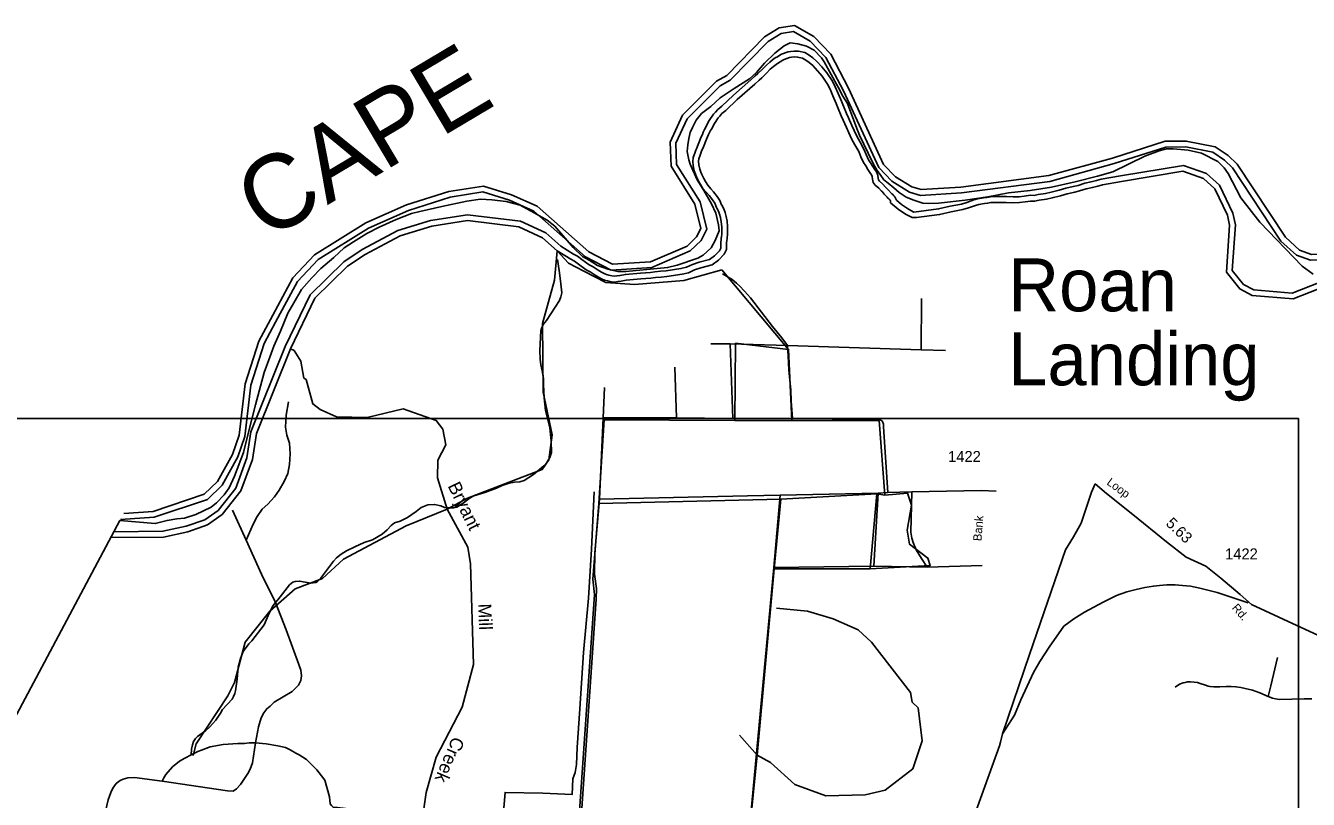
# Model space of a CAD drawing. Extents: x 2225501 to 2309677, y 165449 to 227696.
# Drawn here: x 2251795 to 2266364, y 218912 to 227696 of the extents above; entities that cross this region are included whole.
import ezdxf

# ---------------------------------------------------------------- set-up
doc = ezdxf.new("R2010")
doc.units = 0
for name, color, linetype in [('E_RDY_CMT_EOP', 7, 'Continuous'), ('MARK ENDS WORD SYMBOL CELL', 7, 'Continuous'), ('Old_Level_18', 7, 'Continuous'), ('Old_Level_3', 7, 'Continuous'), ('Old_Level_33', 7, 'Continuous'), ('Old_Level_51', 7, 'Continuous'), ('Old_Level_63', 7, 'Continuous'), ('P_HYD_Drop_Inlet_Grate_2_Wide_Slot_and_Sag_Grates_840_22_48_Dia_Apron_CELL', 7, 'Continuous'), ('P_HYD_Pipe_Pipe_Removal', 7, 'Continuous'), ('P_RDY_Concrete_Monolithic_Island', 7, 'Continuous'), ('P_RDY_Dimension_Text', 7, 'Continuous'), ('Prop Support', 7, 'Continuous'), ('Scratch_Level_1', 7, 'Continuous'), ('Typical Terminator CELL', 7, 'Continuous')]:
    doc.layers.add(name, color=color, linetype=linetype)

msp = doc.modelspace()

# ---------------------------------------------------------------- linework, layer by layer
at = {"layer": 'Old_Level_18'}
msp.add_line((2266181, 224660), (2266624, 224833), dxfattribs=at)
for points in [[(2264160, 226130), (2263429, 225928), (2262423, 225796), (2261960, 225768), (2261832, 225805), (2261633, 225930), (2261485, 226084), (2261083, 226956), (2260885, 227334), (2260705, 227521), (2260515, 227628), (2260376, 227607), (2260229, 227516), (2259798, 227078), (2259682, 227011), (2259308, 226639), (2259180, 226362), (2259189, 226120), (2259456, 225697), (2259533, 225387), (2259468, 225257), (2259343, 225138), (2258907, 224950), (2258444, 224921), (2258154, 225073), (2257568, 225591), (2257289, 225716), (2256989, 225808), (2256618, 225750), (2256144, 225598), (2255687, 225397), (2255119, 225042), (2254882, 224793), (2254659, 224378)], [(2261686, 225714), (2261667, 225754), (2261655, 225765), (2261644, 225779), (2261634, 225786), (2261629, 225792), (2261595, 225827), (2261570, 225856), (2261563, 225864), (2261531, 225898), (2261492, 225930), (2261482, 225944), (2261478, 225966), (2261473, 225998), (2261459, 226035), (2261437, 226066), (2261418, 226096), (2261392, 226137), (2261369, 226174), (2261341, 226233), (2261316, 226295), (2261272, 226373), (2261234, 226441), (2261205, 226505), (2261179, 226564), (2261142, 226651), (2261118, 226700), (2261086, 226780), (2261061, 226839), (2261023, 226926), (2260991, 227000), (2260958, 227065), (2260895, 227160), (2260839, 227227), (2260780, 227289), (2260735, 227331), (2260693, 227359), (2260644, 227390), (2260572, 227405), (2260525, 227407), (2260487, 227404), (2260454, 227398), (2260381, 227372), (2260360, 227359), (2260334, 227343), (2260309, 227330), (2260277, 227307), (2260247, 227282), (2260208, 227248), (2260163, 227202), (2260111, 227153), (2260081, 227127), (2260033, 227081), (2259833, 226906), (2259702, 226783), (2259658, 226745), (2259629, 226713), (2259608, 226690), (2259560, 226619), (2259526, 226554), (2259515, 226537)], [(2259515, 226537), (2259506, 226517), (2259492, 226487), (2259481, 226462), (2259468, 226434), (2259432, 226345), (2259413, 226296), (2259407, 226284), (2259394, 226249), (2259375, 226198), (2259372, 226155), (2259377, 226107), (2259387, 226049), (2259402, 226009), (2259416, 225978), (2259439, 225931), (2259461, 225894), (2259488, 225847), (2259527, 225800), (2259559, 225766), (2259597, 225719), (2259621, 225682), (2259640, 225633), (2259646, 225624), (2259664, 225589), (2259677, 225555), (2259686, 225516), (2259696, 225468), (2259701, 225413), (2259702, 225374), (2259702, 225331), (2259697, 225295), (2259696, 225288), (2259693, 225263), (2259691, 225238), (2259689, 225217)], [(2264160, 226130), (2264747, 226318), (2264972, 226320), (2265278, 226258), (2265413, 226170), (2265504, 226083), (2266053, 225251), (2266229, 225090), (2266387, 225032), (2266613, 225036)], [(2261884, 225580), (2262164, 225616), (2262294, 225646), (2262423, 225670), (2262485, 225690), (2262566, 225717), (2262608, 225728), (2262674, 225741), (2262711, 225745), (2262752, 225753), (2262835, 225755), (2262934, 225756), (2263010, 225752), (2263080, 225753), (2263138, 225760), (2263207, 225770), (2263248, 225768), (2263296, 225779), (2263379, 225792), (2263442, 225804), (2263532, 225828), (2263609, 225850), (2263694, 225869), (2263748, 225883), (2263824, 225906), (2263896, 225923), (2263956, 225937), (2264010, 225954), (2264230, 225992)], [(2266181, 224660), (2265746, 224697), (2265627, 224759), (2265500, 224918), (2265536, 225436), (2265506, 225568), (2265353, 225884), (2265208, 226019), (2264945, 226109), (2264230, 225992)], [(2261686, 225714), (2261744, 225667), (2261821, 225613), (2261884, 225580)], [(2254742, 224052), (2255025, 224640), (2255410, 225015), (2255617, 225154), (2256023, 225371), (2256392, 225485), (2256813, 225548), (2257416, 225476), (2257702, 225344), (2257872, 225193)], [(2257872, 225193), (2258019, 225101), (2258064, 225077), (2258112, 225040), (2258197, 224980), (2258240, 224957), (2258299, 224921), (2258336, 224899), (2258374, 224877), (2258391, 224869), (2258417, 224863), (2258454, 224854), (2258485, 224851), (2258510, 224854), (2258546, 224861), (2258607, 224872), (2258779, 224887), (2258891, 224894), (2258942, 224900), (2259006, 224907), (2259071, 224914), (2259238, 224938), (2259301, 224954), (2259369, 224983), (2259446, 225009), (2259563, 225040)], [(2259563, 225040), (2259619, 225083), (2259676, 225140), (2259690, 225168), (2259689, 225217)], [(2254659, 224378), (2254633, 224330), (2254503, 224089), (2254353, 223615), (2254283, 223032), (2254205, 222801), (2254025, 222480), (2253859, 222318), (2253256, 222115), (2252872, 222088)], [(2252798, 221950), (2253354, 221955), (2253618, 222013), (2253829, 222086), (2253980, 222193), (2254182, 222446), (2254307, 222788), (2254354, 223083), (2254742, 224052)]]:
    msp.add_lwpolyline(points, dxfattribs=at)
at = {"layer": 'Old_Level_3'}
for p, q in [((2261970, 224598), (2261968, 224016)), ((2259797, 224082), (2259579, 224082)), ((2260447, 224063), (2259797, 224082)), ((2259797, 224082), (2259828, 223235)), ((2261968, 224016), (2260447, 224063)), ((2262242, 224008), (2261968, 224016)), ((2259188, 223242), (2259169, 223819)), ((2258354, 223243), (2258369, 223587)), ((2258354, 223243), (2258311, 222319)), ((2259188, 223242), (2258354, 223243)), ((2259828, 223235), (2259188, 223242)), ((2259995, 223235), (2259828, 223235)), ((2260505, 223234), (2259995, 223235)), ((2259995, 222357), (2258311, 222319)), ((2260366, 222366), (2259995, 222357)), ((2260366, 222366), (2260291, 221543)), ((2260366, 222366), (2261478, 222388)), ((2261429, 221560), (2261478, 222388)), ((2261478, 222388), (2261588, 222397)), ((2261588, 222397), (2261859, 222404)), ((2254298, 221856), (2254144, 222194)), ((2260291, 221543), (2259848, 216791)), ((2260291, 221543), (2261429, 221560)), ((2261429, 221560), (2262034, 221549)), ((2262034, 221549), (2262658, 221566))]:
    msp.add_line(p, q, dxfattribs=at)
for points in [[(2257853, 224916), (2257836, 225040)], [(2254631, 221147), (2254660, 221179), (2254793, 221348), (2254829, 221379), (2254857, 221387), (2254906, 221391), (2255035, 221366), (2255090, 221375), (2255110, 221385), (2255144, 221419), (2255188, 221481), (2255291, 221616), (2255326, 221655), (2255380, 221697), (2255440, 221734), (2255533, 221778), (2255641, 221827), (2255734, 221860), (2255844, 221921), (2255899, 221971), (2255947, 222022), (2255985, 222052), (2256050, 222072), (2256132, 222111), (2256231, 222180), (2256287, 222226), (2256363, 222257), (2256439, 222260), (2256509, 222244), (2256551, 222226), (2256595, 222221), (2256655, 222221), (2256693, 222230), (2256763, 222276), (2256844, 222337), (2256886, 222359), (2257010, 222396), (2257141, 222445), (2257207, 222474), (2257288, 222500), (2257346, 222513), (2257406, 222515), (2257458, 222532), (2257562, 222601), (2257679, 222697), (2257716, 222736), (2257748, 222792), (2257768, 222848), (2257764, 222980), (2257749, 223130), (2257700, 223327), (2257685, 223471), (2257675, 223623), (2257675, 223689), (2257662, 223777), (2257647, 223845), (2257639, 223909), (2257634, 224009), (2257646, 224231), (2257652, 224257), (2257672, 224303), (2257709, 224349), (2257859, 224574), (2257875, 224618), (2257885, 224664), (2257870, 224800), (2257853, 224916)], [(2259708, 224877), (2259819, 224814), (2259869, 224774), (2259907, 224739), (2259960, 224683), (2260026, 224606), (2260279, 224280), (2260384, 224153), (2260447, 224063)], [(2260447, 224063), (2260453, 224003), (2260454, 223947), (2260463, 223790), (2260485, 223556), (2260490, 223434), (2260505, 223234)], [(2254779, 223426), (2254752, 223274), (2254746, 223139), (2254763, 223046), (2254790, 222954), (2254801, 222835), (2254790, 222715), (2254773, 222612), (2254730, 222520), (2254676, 222422), (2254622, 222346), (2254546, 222265), (2254481, 222205), (2254426, 222124), (2254377, 222037), (2254298, 221856)], [(2261588, 222397), (2261540, 223143), (2261539, 223173), (2261527, 223203), (2261501, 223224), (2261455, 223232), (2261407, 223230), (2260505, 223234)], [(2258253, 222403), (2258221, 221754), (2258188, 221195), (2258132, 220579), (2258091, 219939), (2258059, 219501), (2258051, 219307), (2258035, 219217), (2258010, 219144), (2258002, 218966), (2257670, 218982), (2257241, 218990), (2257079, 217094), (2256973, 215935), (2256868, 214921), (2256860, 214840)], [(2261859, 222404), (2261849, 221944), (2261860, 221878), (2261876, 221828), (2261911, 221744), (2261970, 221645), (2262034, 221549)], [(2261859, 222404), (2262649, 222420), (2262820, 222412)], [(2258311, 222319), (2258261, 221709), (2258257, 221469), (2258278, 221307), (2258273, 221183), (2258098, 218590), (2257998, 217156), (2257958, 216666)], [(2254631, 221147), (2254474, 221468), (2254298, 221856)], [(2262890, 219654), (2263026, 219868), (2263098, 220043), (2263244, 220354), (2263315, 220476), (2263421, 220641), (2263587, 220880), (2263700, 220961), (2263820, 221036), (2264033, 221150), (2264184, 221225), (2264304, 221267), (2264409, 221294), (2264507, 221316), (2264605, 221333), (2264675, 221339), (2264757, 221347), (2264850, 221348), (2264935, 221341), (2265025, 221331), (2265131, 221311), (2265328, 221259), (2265680, 221142)], [(2253673, 219416), (2253679, 219482), (2253688, 219530), (2253700, 219568), (2253725, 219604), (2253747, 219625), (2253841, 219693), (2253886, 219734), (2253956, 219812), (2253976, 219846), (2254007, 219892), (2254029, 219933), (2254140, 220048), (2254157, 220080), (2254171, 220114), (2254179, 220144), (2254196, 220276), (2254207, 220412), (2254234, 220510), (2254265, 220592), (2254329, 220677), (2254362, 220711), (2254505, 220892), (2254560, 221025), (2254607, 221111), (2254631, 221147)], [(2254406, 219552), (2254438, 219736), (2254471, 219838), (2254499, 219894), (2254534, 219941), (2254572, 219969), (2254618, 220014), (2254821, 220137), (2254864, 220177), (2254892, 220208), (2254920, 220262), (2254929, 220314), (2254921, 220378), (2254898, 220444), (2254753, 220838), (2254631, 221147)], [(2265907, 220081), (2265939, 220199), (2266012, 220521)], [(2265907, 220081), (2265812, 220123), (2265728, 220151), (2265647, 220170), (2265596, 220181), (2265542, 220190), (2265486, 220195), (2265430, 220195), (2265357, 220191), (2265289, 220191), (2265248, 220192), (2265225, 220196), (2265194, 220207), (2265136, 220226), (2265104, 220238), (2265067, 220243), (2265024, 220246), (2264993, 220245), (2264965, 220239), (2264941, 220234), (2264901, 220218), (2264850, 220186)], [(2266403, 220052), (2266316, 220054), (2266035, 220047), (2265992, 220053), (2265958, 220059), (2265907, 220081)], [(2253346, 219117), (2254088, 219007), (2254150, 219006), (2254188, 219030), (2254234, 219081), (2254319, 219205), (2254346, 219254), (2254373, 219326), (2254406, 219552)], [(2253346, 219117), (2253363, 219156), (2253387, 219194), (2253462, 219280), (2253544, 219347), (2253603, 219381), (2253673, 219416)], [(2253673, 219416), (2253749, 219457), (2253791, 219469), (2253892, 219510), (2254040, 219533), (2254206, 219546), (2254280, 219547), (2254332, 219553), (2254406, 219552)], [(2254406, 219552), (2254528, 219541), (2254658, 219518), (2254746, 219499), (2254800, 219473), (2254865, 219436), (2254901, 219418), (2254983, 219363), (2255102, 219248), (2255156, 219178), (2255191, 219129), (2255244, 218939), (2255253, 218861), (2255267, 218841), (2255287, 218823), (2255307, 218818), (2255337, 218818), (2255753, 218769)], [(2252643, 218484), (2252670, 218612), (2252685, 218712), (2252732, 218907), (2252763, 218989), (2252786, 219039), (2252822, 219091), (2252870, 219126), (2252904, 219142), (2252956, 219156), (2253031, 219161), (2253346, 219117)]]:
    msp.add_lwpolyline(points, dxfattribs=at)
at = {"layer": 'Old_Level_33'}
for points in [[(2263944, 222495), (2263902, 222401), (2263782, 222047), (2263698, 221893), (2263607, 221746), (2263196, 220557), (2262890, 219654)], [(2266578, 220728), (2266027, 220979), (2265717, 221126), (2265589, 221237), (2265371, 221424), (2265200, 221558), (2264977, 221663), (2264754, 221837), (2264371, 222147), (2264070, 222386), (2263944, 222495)], [(2262890, 219654), (2262869, 219562), (2262857, 219519), (2262522, 218596), (2262202, 217703), (2262033, 217188), (2261762, 216419), (2260197, 211949), (2260121, 211814), (2260069, 211762), (2259986, 211722), (2259866, 211664), (2259693, 211606), (2259466, 211514), (2259333, 211475), (2259261, 211462), (2259169, 211468), (2258985, 211468), (2258808, 211471), (2258716, 211462), (2258607, 211410)]]:
    msp.add_lwpolyline(points, dxfattribs=at)
at = {"layer": 'Old_Level_51'}
for points in [[(2252865, 222076), (2253266, 222042), (2253401, 222079), (2253513, 222098), (2253599, 222104), (2253727, 222147), (2253900, 222231), (2253964, 222279), (2254051, 222368), (2254106, 222450), (2254167, 222583), (2254269, 222849), (2254319, 223052), (2254404, 223390), (2254503, 223757), (2254570, 223934), (2254613, 224058), (2254689, 224228), (2254772, 224431), (2254839, 224550), (2254928, 224702), (2255046, 224833), (2255148, 224938), (2255294, 225065), (2255411, 225172), (2255517, 225243), (2255670, 225338), (2255811, 225409), (2256005, 225497), (2256176, 225564), (2256272, 225587), (2256521, 225641), (2256807, 225703), (2256960, 225726), (2257088, 225719), (2257253, 225701), (2257413, 225658), (2257569, 225571), (2257720, 225489), (2257806, 225419), (2258014, 225177), (2258121, 225076), (2258195, 225033), (2258290, 224974), (2258408, 224931), (2258520, 224905), (2258612, 224904), (2258850, 224926), (2259086, 224950), (2259196, 224975), (2259431, 225055), (2259490, 225091), (2259582, 225172), (2259625, 225258), (2259670, 225365), (2259666, 225434), (2259635, 225566), (2259586, 225674), (2259497, 225825), (2259422, 225946), (2259342, 226122), (2259326, 226174), (2259309, 226267), (2259315, 226341), (2259328, 226413), (2259341, 226482), (2259369, 226540), (2259412, 226624), (2259473, 226699), (2259579, 226777), (2259684, 226878), (2259841, 226981), (2260018, 227091), (2260095, 227165), (2260188, 227271), (2260306, 227382), (2260410, 227465), (2260477, 227502), (2260566, 227490), (2260664, 227462), (2260750, 227419), (2260835, 227329), (2260864, 227286), (2261024, 226999), (2261075, 226897), (2261130, 226812), (2261236, 226527), (2261267, 226453), (2261366, 226250), (2261425, 226125), (2261466, 226051), (2261502, 226005), (2261543, 225946), (2261591, 225906), (2261657, 225853), (2261718, 225801), (2261796, 225750), (2261884, 225713), (2261985, 225681)], [(2261985, 225681), (2262053, 225676), (2262165, 225681), (2262466, 225715), (2262724, 225753), (2262959, 225799), (2263205, 225825), (2263447, 225863), (2263716, 225923), (2263969, 225989), (2264143, 226035), (2264508, 226216), (2264670, 226275), (2264753, 226296), (2264827, 226299), (2264998, 226284), (2265152, 226249), (2265335, 226154), (2265406, 226083), (2265453, 226018), (2265598, 225741), (2265813, 225466), (2266295, 224967), (2266419, 224875)], [(2252865, 222076), (2251537, 219581), (2249903, 216515), (2248210, 213337), (2246231, 209621), (2243743, 204951), (2241922, 201533), (2239717, 197394), (2237003, 192299), (2234601, 187789), (2232019, 182943), (2229513, 178250), (2226734, 173036), (2226255, 172151), (2225501, 170758)]]:
    msp.add_lwpolyline(points, dxfattribs=at)
at = {"layer": 'Old_Level_63'}
msp.add_line((2266191, 224593), (2266578, 224745), dxfattribs=at)
for points in [[(2264141, 226193), (2263416, 225993), (2262417, 225861), (2261968, 225834), (2261859, 225866), (2261675, 225981), (2261540, 226121), (2261142, 226985), (2260939, 227373), (2260746, 227573), (2260528, 227696), (2260353, 227670), (2260188, 227568), (2259758, 227130), (2259642, 227064), (2259254, 226678), (2259114, 226375), (2259125, 226100), (2259395, 225671), (2259464, 225394), (2259415, 225297), (2259307, 225194), (2258892, 225015), (2258459, 224988), (2258192, 225127), (2257604, 225647), (2257312, 225777), (2256994, 225875), (2256603, 225814), (2256121, 225660), (2255657, 225456), (2255077, 225093), (2254829, 224832), (2254601, 224409)], [(2261619, 225683), (2261619, 225685), (2261619, 225703), (2261613, 225715), (2261606, 225721), (2261598, 225731), (2261588, 225739), (2261580, 225749), (2261546, 225783), (2261522, 225812), (2261516, 225818), (2261486, 225850), (2261443, 225886), (2261421, 225917), (2261413, 225954), (2261409, 225982), (2261401, 226004), (2261382, 226030), (2261362, 226061), (2261336, 226103), (2261312, 226143), (2261281, 226206), (2261257, 226267), (2261214, 226341), (2261176, 226412), (2261145, 226478), (2261119, 226538), (2261082, 226624), (2261058, 226673), (2261025, 226755), (2261001, 226813), (2260963, 226900), (2260932, 226973), (2260901, 227032), (2260843, 227121), (2260790, 227184), (2260735, 227242), (2260694, 227279), (2260657, 227304), (2260619, 227328), (2260563, 227340), (2260525, 227341), (2260495, 227339), (2260471, 227335), (2260410, 227312), (2260394, 227303), (2260366, 227286), (2260344, 227274), (2260318, 227256), (2260290, 227232), (2260252, 227200), (2260208, 227156), (2260155, 227105), (2260125, 227078), (2260078, 227032), (2259877, 226857), (2259746, 226734), (2259704, 226698), (2259678, 226670), (2259660, 226650), (2259617, 226585), (2259583, 226522), (2259573, 226505)], [(2259573, 226505), (2259566, 226489), (2259552, 226459), (2259540, 226434), (2259528, 226408), (2259493, 226321), (2259473, 226270), (2259467, 226258), (2259455, 226226), (2259440, 226184), (2259438, 226156), (2259442, 226116), (2259451, 226067), (2259463, 226034), (2259475, 226006), (2259497, 225962), (2259517, 225926), (2259542, 225885), (2259576, 225843), (2259608, 225809), (2259651, 225758), (2259679, 225712), (2259700, 225662), (2259703, 225656), (2259724, 225616), (2259740, 225574), (2259750, 225530), (2259761, 225478), (2259767, 225416), (2259767, 225375), (2259768, 225326), (2259762, 225286), (2259761, 225280), (2259758, 225256), (2259756, 225232), (2259754, 225214)], [(2264141, 226193), (2264737, 226384), (2264978, 226385), (2265304, 226320), (2265454, 226222), (2265555, 226125), (2266104, 225294), (2266264, 225147), (2266398, 225098), (2266589, 225101)], [(2266191, 224593), (2265727, 224632), (2265585, 224707), (2265433, 224897), (2265470, 225431), (2265444, 225546), (2265300, 225844), (2265174, 225962), (2264940, 226042), (2264241, 225927)], [(2261914, 225517), (2262176, 225551), (2262307, 225582), (2262439, 225607), (2262505, 225627), (2262585, 225654), (2262623, 225664), (2262685, 225676), (2262721, 225680), (2262759, 225687), (2262837, 225690), (2262933, 225690), (2263009, 225686), (2263085, 225688), (2263147, 225695), (2263210, 225704), (2263254, 225702), (2263308, 225714), (2263390, 225727), (2263456, 225740), (2263550, 225764), (2263626, 225787), (2263710, 225806), (2263765, 225820), (2263841, 225842), (2263911, 225859), (2263973, 225874), (2264025, 225890), (2264241, 225927)], [(2261619, 225685), (2261704, 225614), (2261787, 225557), (2261865, 225516), (2261914, 225517)], [(2254802, 224026), (2255080, 224601), (2255452, 224964), (2255651, 225098), (2256049, 225310), (2256407, 225421), (2256814, 225482), (2257398, 225412), (2257666, 225288), (2257833, 225141)], [(2257833, 225141), (2257986, 225044), (2258028, 225022), (2258073, 224987), (2258163, 224924), (2258207, 224900), (2258265, 224864), (2258303, 224842), (2258343, 224819), (2258370, 224807), (2258402, 224799), (2258444, 224789), (2258486, 224785), (2258520, 224790), (2258558, 224796), (2258616, 224807), (2258783, 224822), (2258897, 224828), (2258949, 224835), (2259013, 224842), (2259079, 224849), (2259251, 224873), (2259323, 224891), (2259393, 224922), (2259465, 224946), (2259592, 224980)], [(2259592, 224980), (2259663, 225034), (2259730, 225101), (2259756, 225153), (2259754, 225214)], [(2254601, 224409), (2254575, 224361), (2254443, 224115), (2254289, 223629), (2254219, 223047), (2254145, 222828), (2253973, 222520), (2253824, 222375), (2253243, 222180), (2252909, 222157)], [(2252763, 221884), (2253362, 221889), (2253636, 221949), (2253860, 222027), (2254026, 222145), (2254240, 222413), (2254371, 222771), (2254418, 223066), (2254802, 224026)]]:
    msp.add_lwpolyline(points, dxfattribs=at)
at = {"layer": 'P_HYD_Pipe_Pipe_Removal'}
msp.add_lwpolyline([(2243856, 191238), (2266254, 191238), (2266254, 223234), (2243856, 223234)], close=True, dxfattribs=at)
at = {"layer": 'Prop Support'}
for p, q in [((2259701, 224924), (2260458, 224020)), ((2260458, 224020), (2260498, 223213)), ((2260498, 223213), (2259848, 223215)), ((2261463, 222380), (2260372, 222320)), ((2261463, 222380), (2261386, 221529)), ((2261554, 222365), (2261463, 222380)), ((2260372, 222320), (2258306, 222271)), ((2260372, 222320), (2260295, 221531)), ((2260295, 221531), (2260104, 219412)), ((2261386, 221529), (2260295, 221531)), ((2259902, 219642), (2260104, 219412)), ((2260104, 219412), (2259764, 216119))]:
    msp.add_line(p, q, dxfattribs=at)
for points in [[(2257833, 225141), (2257803, 224807), (2257665, 224314), (2257671, 223533), (2257775, 223049), (2257736, 222765), (2257662, 222658), (2256815, 222333), (2256583, 222207)], [(2257833, 225141), (2257959, 225001), (2258135, 224909), (2258383, 224780), (2258711, 224756), (2259269, 224801), (2259701, 224924)], [(2260458, 224020), (2259858, 224091), (2259848, 223215)], [(2259848, 223215), (2258365, 223221), (2258306, 222271)], [(2260498, 223213), (2261489, 223213), (2261554, 222365)], [(2261554, 222365), (2261812, 222390), (2261855, 222251), (2261807, 221967), (2261834, 221809), (2262043, 221651), (2262069, 221568), (2261386, 221529)], [(2256583, 222207), (2256118, 222019), (2255404, 221639), (2255165, 221421), (2254857, 221302), (2254568, 221049), (2254288, 220697), (2254166, 220237), (2254093, 220087), (2253731, 219543), (2253698, 219409)], [(2258306, 222271), (2258238, 221413), (2258257, 221239), (2257936, 216647)], [(2260104, 219412), (2260255, 219331), (2260531, 219082), (2260882, 218951), (2261332, 218965), (2261557, 219016), (2261871, 219260), (2261977, 219576), (2261932, 219950), (2261865, 220017), (2261847, 220126), (2261401, 220696), (2261250, 220836), (2260966, 220960), (2260674, 221048), (2260324, 221081)]]:
    msp.add_lwpolyline(points, dxfattribs=at)
at = {"layer": 'Typical Terminator CELL'}
for points in [[(2256583, 222207), (2256472, 222563), (2256478, 222763), (2256568, 222938), (2256534, 223116), (2256458, 223213), (2256082, 223345), (2255675, 223248), (2255325, 223255), (2255141, 223337), (2255057, 223401), (2254980, 223678), (2254955, 223695), (2254920, 223886), (2254844, 224009), (2254802, 224026)], [(2256279, 218539), (2256342, 218990), (2256456, 219392), (2256751, 219960), (2256880, 220443), (2256846, 221585), (2256819, 221776), (2256583, 222207)]]:
    msp.add_lwpolyline(points, dxfattribs=at)

# ---------------------------------------------------------------- texts
at = {"layer": 'E_RDY_CMT_EOP'}
for p in [(2262272, 222742), (2265418, 221636)]:
    msp.add_text('1422', height=125, dxfattribs=at).set_placement(p)
at = {"layer": 'MARK ENDS WORD SYMBOL CELL'}
for s, rotation, p in [('Loop', 323.5733, (2264066, 222494)), ('Bank', 85.3255, (2262650, 221841)), ('Rd.', 311.0833, (2265490, 221082))]:
    msp.add_text(s, height=95, rotation=rotation, dxfattribs=at).set_placement(p)
at = {"layer": 'P_HYD_Drop_Inlet_Grate_2_Wide_Slot_and_Sag_Grates_840_22_48_Dia_Apron_CELL'}
msp.add_text('CAPE', height=840, rotation=30.7387, dxfattribs=at).set_placement((2254524, 225242))
at = {"layer": 'P_RDY_Concrete_Monolithic_Island'}
for s, p in [('Roan', (2262954, 224453)), ('Landing', (2262954, 223613))]:
    msp.add_text(s, height=600, dxfattribs=at).set_placement(p)
at = {"layer": 'P_RDY_Dimension_Text'}
msp.add_text('5.63', height=125, rotation=316.2445, dxfattribs=at).set_placement((2264737, 222034))
at = {"layer": 'Scratch_Level_1'}
for s, rotation, p in [('Bryant', 296.1395, (2256585, 222471)), ('Mill', 272.1597, (2256934, 221132)), ('Creek', 246.8981, (2256648, 219635))]:
    msp.add_text(s, height=150, rotation=rotation, dxfattribs=at).set_placement(p)

doc.saveas('drawing.dxf')
